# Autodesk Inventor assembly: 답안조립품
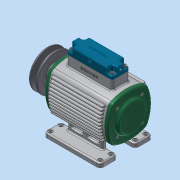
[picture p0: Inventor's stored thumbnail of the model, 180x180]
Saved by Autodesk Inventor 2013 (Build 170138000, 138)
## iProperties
Created: 2015-11
Part Number: 답안조립품
Document SubType Name: Assembly
Designer: dgall
Mass: 3987.74 g
Surface Area: 3184.97 cm^2
Volume: 1076.1 cm^3
Density: 3.70572 g/cm^3
Author: dgall
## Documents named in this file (18)
- C:\Users\dgall\Desktop\351109V1012\답안조립품.iam
- C:\Users\dgall\Desktop\351109V1012\1. 본체.ipt
- C:\Users\dgall\Desktop\351109V1012\4. 베어링 6203.ipt
- C:\Users\dgall\Desktop\351109V1012\2. 뒷커버.ipt
- C:\Users\dgall\Desktop\351109V1012\6. 볼트 M4 x 12.ipt
- C:\Users\dgall\Desktop\351109V1012\7. 축.ipt
- C:\Users\dgall\Desktop\351109V1012\12. 키 - 5 x 5 x 18.ipt
- C:\Users\dgall\Desktop\351109V1012\3. 앞커버.ipt
- C:\Users\dgall\Desktop\351109V1012\5. 오일실 17 30 8.ipt
- C:\Users\dgall\Desktop\351109V1012\11. V-벨트풀리.ipt
- C:\Users\dgall\Desktop\351109V1012\13. 멈춤나사 M4x5.ipt
- C:\Users\dgall\Desktop\351109V1012\14. 슬라이드.ipt
- C:\Users\dgall\Desktop\351109V1012\15. 스프링1.ipt
- C:\Users\dgall\Desktop\351109V1012\16. 스프링2.ipt
- C:\Users\dgall\Desktop\351109V1012\17. 스프링3.ipt
- C:\Users\dgall\Desktop\351109V1012\8. 부시.ipt
- C:\Users\dgall\Desktop\351109V1012\9. 헤더커버.ipt
- C:\Users\dgall\Desktop\351109V1012\10. 볼트 M4 x 16.ipt
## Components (32 placed, 17 different names)
1. 1. 본체:1
2. 7-베어링 6203:1
3. 2. 뒷커버:1
4. 6. 볼트 M4 x 12:1
5. 6. 볼트 M4 x 12:2
6. 6. 볼트 M4 x 12:3
7. 6. 볼트 M4 x 12:4
8. 7. 축:1
9. 12. 키 - 5 x 5 x 18:1
10. 3. 앞커버:1
11. 7-베어링 6203:2
12. 5. 오일실 17 30 8:1
13. 6. 볼트 M4 x 12:5
14. 6. 볼트 M4 x 12:6
15. 6. 볼트 M4 x 12:7
16. 6. 볼트 M4 x 12:8
17. 11. V-벨트풀리:1
18. 13. 멈춤나사 M4x5:1
19. 14. 슬라이드:1
20. 14. 슬라이드:2
21. 14. 슬라이드:3
22. 15. 스프링1:1
23. 16. 스프링2:1
24. 17. 스프링3:1
25. 8. 부시:1
26. 8. 부시:2
27. 8. 부시:3
28. 9. 헤더커버:1
29. 10. 볼트 M4 x 16:1
30. 10. 볼트 M4 x 16:2
31. 10. 볼트 M4 x 16:3
32. 10. 볼트 M4 x 16:4
